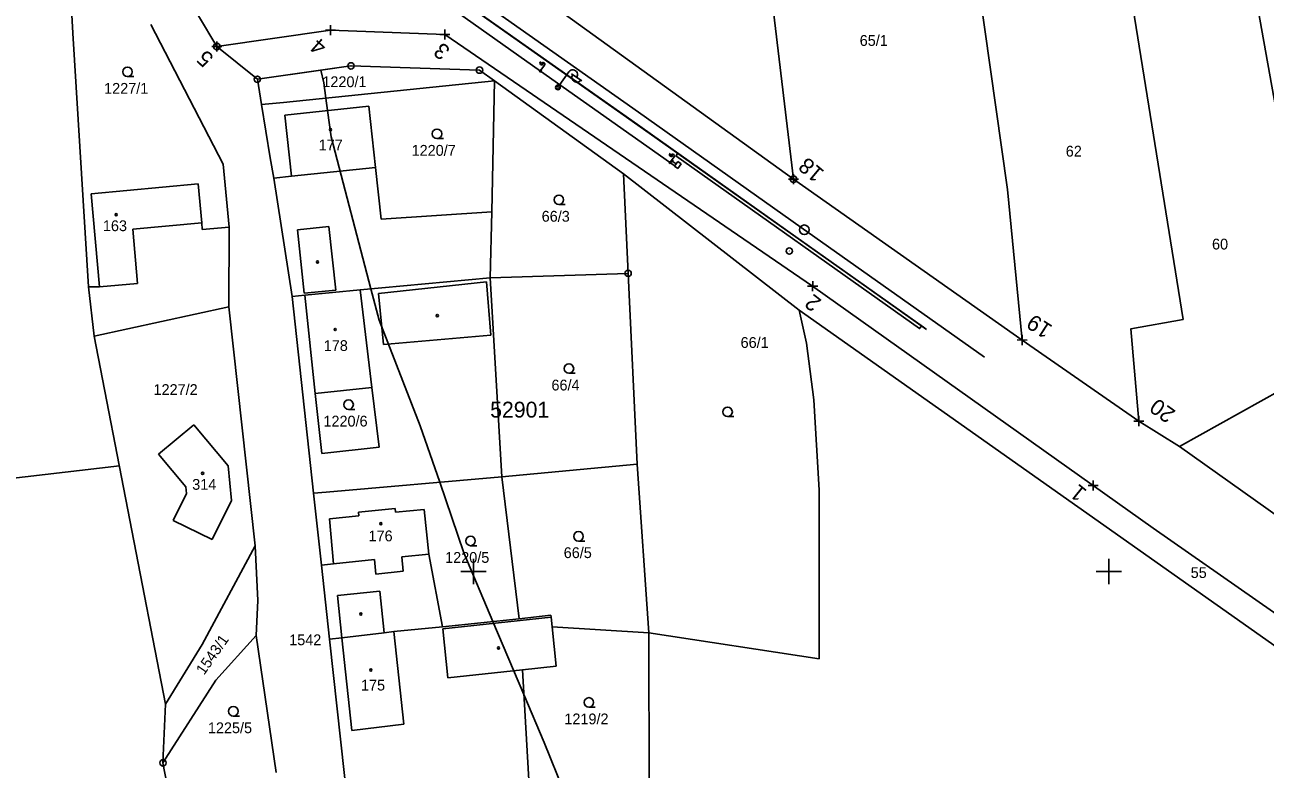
# Model space of a CAD drawing. Extents: x -777175 to -776673, y -1110537 to -1110036.
# Drawn here: x -776970.6 to -776775.4, y -1110431.1 to -1110313.9 of the extents above; entities that cross this region are included whole.
import ezdxf

# ---------------------------------------------------------------- set-up
doc = ezdxf.new("R2010")
doc.units = 0
for name, color, linetype in [('BPEJ', 7, 'Continuous'), ('GD_Demolice', 7, 'Continuous'), ('GD_Nový stav', 7, 'Continuous'), ('GD_Starý stav', 7, 'Continuous'), ('Groma (60)', 7, 'Continuous'), ('Katastr_HRANICE DRÁHY', 7, 'Continuous'), ('Katastr_Hranice parcel', 7, 'Continuous'), ('Katastr_Parcelní čísla', 7, 'Continuous'), ('Katastr_Slučkované čáry', 7, 'Continuous'), ('Katastr_Značky kultur', 7, 'Continuous'), ('Vrstva 7', 7, 'Continuous'), ('čtvercová síť', 7, 'Continuous')]:
    doc.layers.add(name, color=color, linetype=linetype)

# ---------------------------------------------------------------- blocks, each defined once
blk = doc.blocks.new('POINT_DISPLAY')
for p, q in [((-0.56, -0.56), (0.56, 0.56)), ((-0.56, 0.56), (0.56, -0.56))]:
    blk.add_line(p, q)
blk = doc.blocks.new('C691')
at = {"layer": 'čtvercová síť'}
for p, q in [((0, 0.5), (0, -0.5)), ((-0.5, 0), (0.5, 0))]:
    blk.add_line(p, q, dxfattribs=at)

msp = doc.modelspace()

# ---------------------------------------------------------------- linework, layer by layer
at = {"layer": 'BPEJ'}
for points in [[(-776780.63, -1110277.66), (-776801.34, -1110279.1), (-776814.49, -1110280.25), (-776823.89, -1110281.93), (-776826.29, -1110267.5), (-776831.4, -1110267.85), (-776830.95, -1110273.53), (-776856.55, -1110275.29), (-776856.32, -1110281.19), (-776854.31, -1110299.08), (-776849.62, -1110338.22), (-776894.76, -1110305.65), (-776896.59, -1110304.32), (-776903.91, -1110299.01), (-776906.52, -1110296.78), (-776914.36, -1110290.06), (-776923.15, -1110282.87), (-776931.82, -1110275.9)], [(-776942.64, -1110471.49), (-776943.89, -1110463.76), (-776944.49, -1110457.52), (-776946.46, -1110445.63), (-776946.62, -1110444.42), (-776947.54, -1110437.37), (-776947.6, -1110436.89), (-776948.9, -1110430.12), (-776948.48, -1110420.89), (-776959.71, -1110362.93), (-776960.61, -1110355.15), (-776963.07, -1110315.22), (-776964.17, -1110295.07), (-776960.44, -1110293.63), (-776956.24, -1110294.15), (-776954.44, -1110298.36), (-776953.88, -1110294.2), (-776949.89, -1110285), (-776940.9, -1110291.45)], [(-776940.9, -1110291.45), (-776945.85, -1110300.04), (-776946.2, -1110307.65), (-776940.41, -1110317.34), (-776934.03, -1110322.5), (-776924.02, -1110321.07)], [(-776924.02, -1110321.07), (-776919.29, -1110320.39), (-776899.05, -1110321.06), (-776896.7, -1110322.75), (-776876.4, -1110337.37), (-776875.66, -1110353.06), (-776874.23, -1110383.12), (-776872.38, -1110409.66), (-776872.36, -1110434.4)], [(-776871.27, -1110465.42), (-776878.74, -1110452.04), (-776879.88, -1110449.23), (-776883.66, -1110439.87), (-776885.8, -1110434.57), (-776888.9, -1110426.9), (-776892.08, -1110419.38), (-776896.95, -1110407.86), (-776901.52, -1110397.06), (-776905.33, -1110385.94), (-776908.38, -1110377.06), (-776914.87, -1110360.44), (-776916.16, -1110355.5), (-776922.42, -1110331.54), (-776922.97, -1110327.43), (-776923.23, -1110325.46), (-776923.55, -1110323.06), (-776924.02, -1110321.07)]]:
    msp.add_lwpolyline(points, dxfattribs=at)
at = {"layer": 'GD_Demolice'}
for p, q in [((-776886.5, -1110323.47), (-776884.98, -1110321.33)), ((-776884.55, -1110321.64), (-776882.96, -1110322.76)), ((-776887.07, -1110323.67), (-776886.42, -1110323.55)), ((-776887.05, -1110323.94), (-776886.34, -1110323.82))]:
    msp.add_line(p, q, dxfattribs=at)
msp.add_lwpolyline([(-776868.13, -1110334.57), (-776829.78, -1110361.74), (-776829.49, -1110361.33), (-776867.84, -1110334.16)], close=True, dxfattribs=at)
msp.add_circle((-776886.71, -1110323.78), 0.375, dxfattribs=at)
msp.add_circle((-776886.71, -1110323.78), 0.375, dxfattribs=at)
for centre, start, end in [((-776884.37, -1110321.76), 324.7342, 144.7342), ((-776883.76, -1110322.21), 144.0316, 325.4368)]:
    msp.add_arc(centre, 0.75, start, end, dxfattribs=at)
at = {"layer": 'GD_Nový stav'}
for p, q in [((-776909.86, -1110306.76), (-776889.46, -1110321.21)), ((-776888.97, -1110320.18), (-776889.57, -1110319.75)), ((-776889.38, -1110321.09), (-776888.81, -1110320.29)), ((-776889.48, -1110321.35), (-776889.52, -1110321.08)), ((-776889.46, -1110321.21), (-776868.26, -1110336.2)), ((-776889.38, -1110321.32), (-776889.42, -1110321.08)), ((-776868.58, -1110334.6), (-776869.18, -1110334.17)), ((-776868.13, -1110334.57), (-776867.84, -1110334.16)), ((-776869.09, -1110335.77), (-776869.13, -1110335.5)), ((-776868.98, -1110335.74), (-776869.02, -1110335.5)), ((-776868.99, -1110335.51), (-776868.42, -1110334.71)), ((-776868.59, -1110335.23), (-776868.81, -1110335.53)), ((-776868.7, -1110335.38), (-776868.09, -1110335.81)), ((-776868.09, -1110335.81), (-776868.34, -1110336.17)), ((-776868.34, -1110336.17), (-776867.83, -1110336.53)), ((-776867.84, -1110335.46), (-776868.09, -1110335.81)), ((-776867.33, -1110335.82), (-776867.84, -1110335.46)), ((-776867.83, -1110336.53), (-776867.33, -1110335.82))]:
    msp.add_line(p, q, dxfattribs=at)
for centre in [(-776889.46, -1110321.21), (-776889.46, -1110321.21), (-776869.07, -1110335.63), (-776869.07, -1110335.63)]:
    msp.add_circle(centre, 0.141, dxfattribs=at)
for centre, start, end in [((-776889.27, -1110319.97), 143.98, 325.3852), ((-776889.04, -1110320.13), 324.6826, 144.6826), ((-776868.88, -1110334.39), 143.98, 325.3852), ((-776868.65, -1110334.55), 324.6826, 144.6826)]:
    msp.add_arc(centre, 0.281, start, end, dxfattribs=at)
at = {"layer": 'GD_Starý stav'}
for points in [[(-776933.32, -1110287.93), (-776932.41, -1110288.39), (-776916.53, -1110299.75), (-776903.36, -1110309.07), (-776875.06, -1110329), (-776849.25, -1110347.3), (-776828.68, -1110361.9)], [(-776828.68, -1110361.9), (-776829.18, -1110361.55), (-776849.26, -1110347.33), (-776875, -1110329.07), (-776903.43, -1110309.03), (-776920.48, -1110296.98), (-776932.53, -1110288.41), (-776933.32, -1110287.93)], [(-776819.55, -1110366.24), (-776848.4, -1110345.85), (-776874.05, -1110327.7), (-776902.43, -1110307.63), (-776922.25, -1110293.6), (-776926.74, -1110290.42), (-776929.88, -1110288.2)]]:
    msp.add_lwpolyline(points, dxfattribs=at)
at = {"layer": 'Katastr_HRANICE DRÁHY'}
for points in [[(-776849.62, -1110338.22), (-776894.76, -1110305.65)], [(-776946.2, -1110307.65), (-776940.41, -1110317.34)], [(-776757.91, -1110417.68), (-776792.98, -1110393.16), (-776846.61, -1110355.09), (-776904.52, -1110315.47), (-776922.51, -1110314.75), (-776940.41, -1110317.34)], [(-776849.62, -1110338.22), (-776813.64, -1110363.55), (-776795.25, -1110376.34), (-776788.84, -1110380.33), (-776748.99, -1110408.66)]]:
    msp.add_lwpolyline(points, dxfattribs=at)
at = {"layer": 'Katastr_Hranice parcel'}
msp.add_line((-776766.43, -1110367.83), (-776782.5, -1110277.79), dxfattribs=at)
for points in [[(-776795.25, -1110376.34), (-776796.53, -1110361.81), (-776788.29, -1110360.31), (-776801.34, -1110279.1)], [(-776813.64, -1110363.55), (-776815.92, -1110339.86), (-776822.21, -1110295.34), (-776823.89, -1110281.93)], [(-776963.07, -1110315.22), (-776964.17, -1110295.07)], [(-776854.31, -1110299.08), (-776849.62, -1110338.22)], [(-776950.83, -1110313.89), (-776939.43, -1110335.86)], [(-776960.61, -1110355.15), (-776963.07, -1110315.22)], [(-776940.41, -1110317.34), (-776934.03, -1110322.5)], [(-776934.03, -1110322.5), (-776919.29, -1110320.39)], [(-776919.29, -1110320.39), (-776899.05, -1110321.06)], [(-776933.39, -1110326.49), (-776934.03, -1110322.5)], [(-776899.05, -1110321.06), (-776896.7, -1110322.75)], [(-776896.7, -1110322.75), (-776929.92, -1110326.14)], [(-776896.7, -1110322.75), (-776897.12, -1110343.35)], [(-776896.7, -1110322.75), (-776876.4, -1110337.37)], [(-776929.92, -1110326.14), (-776933.39, -1110326.49)], [(-776931.99, -1110334.85), (-776933.39, -1110326.49)], [(-776916.46, -1110326.75), (-776929.7, -1110328.14)], [(-776929.7, -1110328.14), (-776928.66, -1110337.76)], [(-776916.46, -1110326.75), (-776915.42, -1110336.37)], [(-776939.43, -1110335.86), (-776938.47, -1110345.76)], [(-776931.45, -1110338.05), (-776931.99, -1110334.85)], [(-776928.66, -1110337.76), (-776931.45, -1110338.05)], [(-776928.57, -1110356.7), (-776931.45, -1110338.05)], [(-776915.42, -1110336.37), (-776914.54, -1110344.5)], [(-776876.4, -1110337.37), (-776875.66, -1110353.06)], [(-776876.4, -1110337.37), (-776848.72, -1110358.87), (-776847.56, -1110364.06), (-776846.44, -1110372.99), (-776845.59, -1110387.18), (-776845.59, -1110413.73), (-776872.38, -1110409.66)], [(-776943.34, -1110338.96), (-776960.2, -1110340.54)], [(-776942.8, -1110345.12), (-776943.34, -1110338.96)], [(-776960.2, -1110340.54), (-776958.86, -1110355.2)], [(-776897.12, -1110343.35), (-776914.54, -1110344.5)], [(-776897.39, -1110353.76), (-776897.12, -1110343.35)], [(-776942.8, -1110345.12), (-776942.71, -1110346.13)], [(-776942.71, -1110346.13), (-776938.47, -1110345.76)], [(-776938.51, -1110358.35), (-776938.47, -1110345.76)], [(-776897.39, -1110353.76), (-776917.87, -1110355.66)], [(-776875.66, -1110353.06), (-776897.39, -1110353.76)], [(-776895.52, -1110385.09), (-776897.39, -1110353.76)], [(-776875.66, -1110353.06), (-776874.23, -1110383.12)], [(-776959.71, -1110362.93), (-776960.61, -1110355.15)], [(-776958.86, -1110355.2), (-776960.61, -1110355.15)], [(-776917.87, -1110355.66), (-776926.58, -1110356.51)], [(-776926.58, -1110356.51), (-776928.57, -1110356.7)], [(-776928.57, -1110356.7), (-776925.21, -1110387.65)], [(-776959.71, -1110362.93), (-776938.51, -1110358.35)], [(-776938.51, -1110358.35), (-776934.37, -1110395.94)], [(-776848.72, -1110358.87), (-776760.96, -1110420.76)], [(-776948.48, -1110420.89), (-776959.71, -1110362.93)], [(-776746.53, -1110364.29), (-776758.73, -1110365.29), (-776766.43, -1110367.83), (-776788.84, -1110380.33)], [(-776915.99, -1110371.01), (-776924.93, -1110371.95)], [(-776915.99, -1110371.01), (-776914.84, -1110380.44)], [(-776924.93, -1110371.95), (-776923.89, -1110381.39)], [(-776949.58, -1110381.53), (-776944.06, -1110376.89)], [(-776944.06, -1110376.89), (-776938.61, -1110383.37)], [(-776914.84, -1110380.44), (-776923.89, -1110381.39)], [(-776945.3, -1110386.64), (-776949.58, -1110381.53)], [(-776874.23, -1110383.12), (-776895.52, -1110385.09)], [(-776874.23, -1110383.12), (-776872.38, -1110409.66)], [(-777023.74, -1110391.3), (-776955.76, -1110383.34)], [(-776938.61, -1110383.37), (-776938.08, -1110388.81)], [(-776895.52, -1110385.09), (-776923.22, -1110387.48)], [(-776895.52, -1110385.09), (-776892.79, -1110407.42)], [(-776945.17, -1110387.71), (-776945.3, -1110386.64)], [(-776947.29, -1110391.94), (-776945.17, -1110387.71)], [(-776938.08, -1110388.81), (-776941.13, -1110394.94)], [(-776923.22, -1110387.48), (-776925.21, -1110387.65)], [(-776925.21, -1110387.65), (-776923.96, -1110398.98)], [(-776912.36, -1110390.08), (-776918.11, -1110390.66)], [(-776918.11, -1110390.66), (-776918.05, -1110391.25)], [(-776912.3, -1110390.67), (-776912.36, -1110390.08)], [(-776907.75, -1110390.21), (-776912.3, -1110390.67)], [(-776907.75, -1110390.21), (-776907.04, -1110397.24)], [(-776941.13, -1110394.94), (-776947.29, -1110391.94)], [(-776918.05, -1110391.25), (-776922.7, -1110391.72)], [(-776922.7, -1110391.72), (-776922.03, -1110398.78)], [(-776942.73, -1110411.46), (-776934.37, -1110395.94)], [(-776933.98, -1110404.58), (-776934.37, -1110395.94)], [(-776923.96, -1110398.98), (-776922.03, -1110398.78)], [(-776907.04, -1110397.24), (-776904.88, -1110408.71)], [(-776923.96, -1110398.98), (-776922.67, -1110410.67)], [(-776934.24, -1110410.08), (-776933.98, -1110404.58)], [(-776904.88, -1110408.71), (-776892.79, -1110407.42)], [(-776892.79, -1110407.42), (-776887.83, -1110406.89)], [(-776887.8, -1110407.19), (-776887.83, -1110406.89)], [(-776887.8, -1110407.19), (-776887.64, -1110408.68)], [(-776934.24, -1110410.08), (-776940.56, -1110417.1)], [(-776931.08, -1110431.61), (-776934.24, -1110410.08)], [(-776922.67, -1110410.67), (-776920.73, -1110410.44)], [(-776920.73, -1110410.44), (-776914.08, -1110409.64)], [(-776914.08, -1110409.64), (-776912.57, -1110409.46)], [(-776912.57, -1110409.46), (-776904.88, -1110408.71)], [(-776887.64, -1110408.68), (-776872.38, -1110409.66)], [(-776887.64, -1110408.68), (-776886.97, -1110414.92)], [(-776872.38, -1110409.66), (-776872.36, -1110434.4)], [(-776948.48, -1110420.89), (-776942.73, -1110411.46)], [(-776922.67, -1110410.67), (-776919.72, -1110437.38)], [(-776892.31, -1110415.49), (-776886.97, -1110414.92)], [(-776891.17, -1110434.64), (-776892.31, -1110415.49)], [(-776940.56, -1110417.1), (-776948.9, -1110430.12)], [(-776948.9, -1110430.12), (-776948.48, -1110420.89)], [(-776947.6, -1110436.89), (-776948.9, -1110430.12)]]:
    msp.add_lwpolyline(points, dxfattribs=at)
at = {"layer": 'Katastr_Slučkované čáry'}
for points in [[(-776915.42, -1110336.37), (-776928.66, -1110337.76)], [(-776953.66, -1110346.08), (-776942.8, -1110345.12)], [(-776952.88, -1110354.65), (-776953.66, -1110346.08)], [(-776927.7, -1110346.2), (-776922.76, -1110345.68)], [(-776922.76, -1110345.68), (-776921.68, -1110355.68)], [(-776927.7, -1110346.2), (-776926.64, -1110356.16)], [(-776958.86, -1110355.2), (-776952.88, -1110354.65)], [(-776921.68, -1110355.68), (-776926.64, -1110356.16)], [(-776917.87, -1110355.66), (-776915.99, -1110371.01)], [(-776897.95, -1110354.4), (-776914.98, -1110356.23)], [(-776897.95, -1110354.4), (-776897.3, -1110362.8)], [(-776926.58, -1110356.51), (-776924.93, -1110371.95)], [(-776914.98, -1110356.23), (-776914.17, -1110364.23)], [(-776897.3, -1110362.8), (-776914.17, -1110364.23)], [(-776915.6, -1110398.12), (-776922.03, -1110398.78)], [(-776915.36, -1110400.39), (-776915.6, -1110398.12)], [(-776907.04, -1110397.24), (-776911.29, -1110397.68)], [(-776911.29, -1110397.68), (-776911.06, -1110399.95)], [(-776911.06, -1110399.95), (-776915.36, -1110400.39)], [(-776921.41, -1110403.78), (-776914.74, -1110403.1)], [(-776921.41, -1110403.78), (-776920.73, -1110410.44)], [(-776914.74, -1110403.1), (-776914.08, -1110409.64)], [(-776904.85, -1110409.01), (-776887.8, -1110407.19)], [(-776919.14, -1110425.01), (-776920.73, -1110410.44)], [(-776910.98, -1110424.03), (-776912.57, -1110409.46)], [(-776904.85, -1110409.01), (-776904.02, -1110416.74)], [(-776904.02, -1110416.74), (-776892.31, -1110415.49)], [(-776910.98, -1110424.03), (-776919.14, -1110425.01)]]:
    msp.add_lwpolyline(points, dxfattribs=at)
at = {"layer": 'Katastr_Značky kultur'}
for p, q in [((-776940.46, -1110317.34), (-776940.36, -1110317.34)), ((-776919.34, -1110320.39), (-776919.24, -1110320.39)), ((-776954.48, -1110322.08), (-776953.48, -1110322.08)), ((-776934.08, -1110322.5), (-776933.98, -1110322.5)), ((-776899.1, -1110321.06), (-776899, -1110321.06)), ((-776905.75, -1110331.84), (-776904.75, -1110331.84)), ((-776849.67, -1110338.22), (-776849.57, -1110338.22)), ((-776886.56, -1110342.22), (-776885.56, -1110342.22)), ((-776875.71, -1110353.06), (-776875.61, -1110353.06)), ((-776884.98, -1110368.79), (-776883.98, -1110368.79)), ((-776919.67, -1110374.47), (-776918.67, -1110374.47)), ((-776860, -1110375.61), (-776859, -1110375.61)), ((-776900.47, -1110395.93), (-776899.47, -1110395.93)), ((-776883.47, -1110395.21), (-776882.47, -1110395.21)), ((-776881.84, -1110421.35), (-776880.84, -1110421.35)), ((-776937.82, -1110422.75), (-776936.82, -1110422.75)), ((-776948.95, -1110430.12), (-776948.85, -1110430.12))]:
    msp.add_line(p, q, dxfattribs=at)
for centre, radius in [((-776940.41, -1110317.34), 0.499), ((-776954.48, -1110321.33), 0.75), ((-776919.29, -1110320.39), 0.499), ((-776899.05, -1110321.06), 0.499), ((-776934.03, -1110322.5), 0.499), ((-776922.51, -1110330.42), 0.175), ((-776905.75, -1110331.09), 0.75), ((-776849.62, -1110338.22), 0.499), ((-776886.56, -1110341.47), 0.75), ((-776956.26, -1110343.82), 0.175), ((-776924.56, -1110351.26), 0.175), ((-776875.66, -1110353.06), 0.499), ((-776905.7, -1110359.7), 0.175), ((-776921.79, -1110361.89), 0.175), ((-776884.98, -1110368.04), 0.75), ((-776919.67, -1110373.72), 0.75), ((-776860, -1110374.86), 0.75), ((-776942.66, -1110384.53), 0.175), ((-776914.6, -1110392.46), 0.175), ((-776900.47, -1110395.18), 0.75), ((-776883.47, -1110394.46), 0.75), ((-776917.74, -1110406.7), 0.175), ((-776896.07, -1110412.03), 0.175), ((-776916.16, -1110415.5), 0.175), ((-776881.84, -1110420.6), 0.75), ((-776937.82, -1110422), 0.75), ((-776948.9, -1110430.12), 0.499)]:
    msp.add_circle(centre, radius, dxfattribs=at)
at = {"layer": 'Vrstva 7'}
msp.add_line((-776850.24, -1110349.57), (-776850.33, -1110349.51), dxfattribs=at)
for centre, radius in [((-776847.92, -1110346.19), 0.75), ((-776850.29, -1110349.54), 0.5)]:
    msp.add_circle(centre, radius, dxfattribs=at)

# ---------------------------------------------------------------- block references
at = {"layer": 'Groma (60)', "rotation": 44.67649342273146}
for p in [(-776922.51, -1110314.75), (-776904.52, -1110315.47), (-776940.41, -1110317.34), (-776849.62, -1110338.22), (-776846.61, -1110355.09), (-776813.64, -1110363.55), (-776795.25, -1110376.34), (-776802.43, -1110386.46)]:
    msp.add_blockref('POINT_DISPLAY', p, dxfattribs=at)
at = {"layer": 'čtvercová síť', "xscale": 4, "yscale": 4}
for p in [(-776899.99, -1110400), (-776799.99, -1110400)]:
    msp.add_blockref('C691', p, dxfattribs=at)

# ---------------------------------------------------------------- texts
at = {"layer": 'BPEJ'}
msp.add_text('52901', height=2.5, dxfattribs=at).set_placement((-776897.38, -1110375.76))
at = {"layer": 'Groma (60)'}
for s, rotation, p in [('4', 138.623, (-776922.92, -1110317.07)), ('5', 137.3788, (-776940.75, -1110318.99)), ('3', 140.8447, (-776903.51, -1110317.74)), ('18', 140.0328, (-776844.63, -1110337.02)), ('2', 141.6188, (-776845.07, -1110357.33)), ('19', 147.0407, (-776808.69, -1110361.39)), ('20', 144.3126, (-776789.32, -1110374.77)), ('1', 140.9303, (-776803.29, -1110387.28))]:
    msp.add_text(s, height=2.5, rotation=rotation, dxfattribs=at).set_placement(p)
at = {"layer": 'Katastr_Parcelní čísla'}
for s, p in [('65/1', (-776839.2, -1110317.24)), ('1220/1', (-776923.8, -1110323.74)), ('1227/1', (-776958.16, -1110324.78)), ('177', (-776924.38, -1110333.69)), ('1220/7', (-776909.75, -1110334.54)), ('62', (-776806.76, -1110334.67)), ('66/3', (-776889.27, -1110344.92)), ('163', (-776958.35, -1110346.41)), ('60', (-776783.73, -1110349.3)), ('178', (-776923.58, -1110365.28)), ('66/1', (-776857.95, -1110364.79)), ('1227/2', (-776950.38, -1110372.2)), ('66/4', (-776887.73, -1110371.49)), ('1220/6', (-776923.63, -1110377.17)), ('314', (-776944.29, -1110387.13)), ('176', (-776916.53, -1110395.24)), ('1220/5', (-776904.47, -1110398.63)), ('66/5', (-776885.8, -1110397.88)), ('55', (-776787.09, -1110401.01)), ('1542', (-776929.02, -1110411.6)), ('175', (-776917.72, -1110418.73)), ('1219/2', (-776885.7, -1110424.05)), ('1225/5', (-776941.82, -1110425.45))]:
    msp.add_text(s, height=1.7, dxfattribs=at).set_placement(p)
msp.add_text('1543/1', height=1.7, rotation=55.0543, dxfattribs=at).set_placement((-776942.42, -1110416.39))

doc.saveas('drawing.dxf')
